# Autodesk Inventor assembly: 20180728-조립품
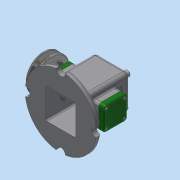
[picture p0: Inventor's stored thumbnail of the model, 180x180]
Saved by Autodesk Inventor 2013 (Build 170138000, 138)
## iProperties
Created: 2018-07
Part Number: 20180728-조립품
Document SubType Name: Assembly
Designer: dgall
Author: dgall
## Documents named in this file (16)
- C:\Users\dgall\Desktop\480707V1008\20180728-조립품.iam
- C:\Users\dgall\Desktop\480707V1008\20180728-본체.ipt
- C:\Users\dgall\Desktop\480707V1008\뒤커버.ipt
- C:\Users\dgall\Desktop\480707V1008\베어링 12x32x10.ipt
- C:\Users\dgall\Desktop\480707V1008\앞커버.ipt
- C:\Users\dgall\Desktop\480707V1008\편심축.ipt
- C:\Users\dgall\Desktop\480707V1008\고정핀 1.2x8.ipt
- C:\Users\dgall\Desktop\480707V1008\링크.ipt
- C:\Users\dgall\Desktop\480707V1008\부시.ipt
- C:\Users\dgall\Desktop\480707V1008\슬라이드.ipt
- C:\Users\dgall\Desktop\480707V1008\핀 5x18.ipt
- C:\Users\dgall\Desktop\480707V1008\V벨트풀리.ipt
- C:\Users\dgall\Desktop\480707V1008\오일 실 12 25 7.ipt
- C:\Users\dgall\Desktop\480707V1008\키 4x4x10.ipt
- C:\Users\dgall\Desktop\480707V1008\멈춤나사 M3x8.ipt
- C:\Users\dgall\Desktop\480707V1008\볼트 M4.ipt
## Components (4 placed, 4 different names)
1. 20180728-본체:1
2. 고정핀 1.2x8:1
3. 핀 5x18:1
4. V벨트풀리:1
